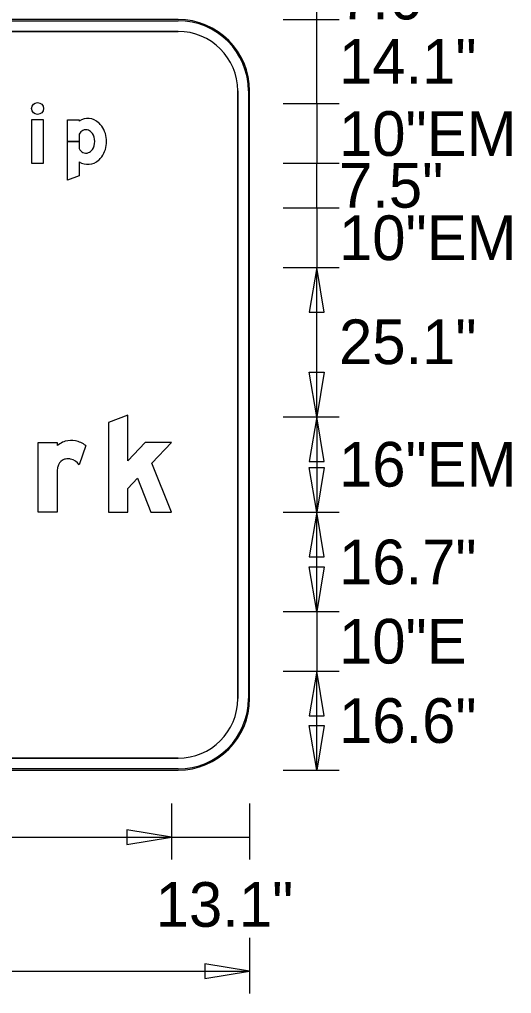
# Model space of a CAD drawing. Extents: x 1806251 to 1809821, y 414895 to 422886.
# Drawn here: x 1809678.349 to 1809679.174, y 414981.376 to 414983.011 of the extents above; entities that cross this region are included whole.
import ezdxf

# ---------------------------------------------------------------- set-up
doc = ezdxf.new("R2010")
doc.units = 0
for name, color, linetype in [('GSBWFILL', 7, 'Continuous'), ('GSCOLORFILL', 7, 'Continuous'), ('GSDIMS', 7, 'Continuous'), ('GSOUTLINE', 7, 'Continuous')]:
    doc.layers.add(name, color=color, linetype=linetype)

msp = doc.modelspace()

# ---------------------------------------------------------------- linework, layer by layer
at = {"layer": 'GSBWFILL'}
for p, q in [((1809678.615, 414983.011), (1809676.574, 414983.011)), ((1809676.574, 414982.991), (1809678.615, 414982.991)), ((1809678.715, 414982.891), (1809678.715, 414981.871)), ((1809678.735, 414981.871), (1809678.735, 414982.891)), ((1809678.4292, 414982.8063), (1809678.4492, 414982.8063)), ((1809678.4492, 414982.8063), (1809678.4292, 414982.8063)), ((1809678.4492, 414982.8183), (1809678.4492, 414982.8063)), ((1809678.4492, 414982.8063), (1809678.4492, 414982.7943)), ((1809678.46, 414982.2958), (1809678.4491, 414982.2632)), ((1809678.615, 414981.771), (1809676.5742, 414981.771)), ((1809676.5742, 414981.751), (1809678.615, 414981.751))]:
    msp.add_line(p, q, dxfattribs=at)
for points in [[(1809678.3692, 414982.7698), (1809678.3892, 414982.7698), (1809678.3892, 414982.8428), (1809678.3692, 414982.8428)], [(1809678.5709, 414982.2663), (1809678.604, 414982.301), (1809678.5598, 414982.301), (1809678.5304, 414982.2701), (1809678.5304, 414982.347), (1809678.4984, 414982.3346), (1809678.4984, 414982.1842), (1809678.5304, 414982.1842), (1809678.5304, 414982.2237), (1809678.5467, 414982.2408), (1809678.5695, 414982.1842), (1809678.604, 414982.1842)]]:
    msp.add_lwpolyline(points, close=True, dxfattribs=at)
for points in [[(1809678.4292, 414982.8063), (1809678.4292, 414982.8428), (1809678.4492, 414982.8428), (1809678.4492, 414982.8404)], [(1809678.4492, 414982.7722), (1809678.4492, 414982.7484), (1809678.4292, 414982.7411), (1809678.4292, 414982.8063)], [(1809678.412, 414982.2488), (1809678.412, 414982.1842), (1809678.38, 414982.1842), (1809678.38, 414982.301), (1809678.412, 414982.301), (1809678.412, 414982.2958)]]:
    msp.add_lwpolyline(points, dxfattribs=at)
for centre, radius, start, end in [((1809678.615, 414982.891), 0.12, 0, 90), ((1809678.615, 414982.891), 0.1, 0, 90), ((1809678.615, 414981.871), 0.12, 270, 0), ((1809678.615, 414981.871), 0.1, 270, 0)]:
    msp.add_arc(centre, radius, start, end, dxfattribs=at)
msp.add_ellipse((1809678.3792, 414982.8616), major_axis=(0, 0.01), ratio=0.999994, dxfattribs=at)
for centre, major_axis, ratio, start_param, end_param in [((1809678.4637, 414982.8186), (0, 0.0262), 0.999998, 5.531582, 6.870178), ((1809678.461, 414982.8136), (0, 0.0317), 0.999998, 5.330424, 5.578482), ((1809678.4603, 414982.8139), (0, 0.012), 0.999998, 5.918977, 7.479923), ((1809678.4596, 414982.812), (0, 0.014), 0.999998, 5.303244, 5.918977), ((1809678.4521, 414982.807), (0, 0.0231), 0.999998, 4.683658, 5.303244), ((1809678.4514, 414982.8063), (0, 0.0437), 0.999998, 4.712389, 5.339507), ((1809678.4521, 414982.8056), (0, 0.0231), 0.999998, 4.121534, 4.74112), ((1809678.4514, 414982.8063), (0, 0.0437), 0.999998, 4.085271, 4.712389), ((1809678.4603, 414982.7987), (0, 0.012), 0.999998, 1.944855, 3.5058), ((1809678.4596, 414982.8006), (0, 0.014), 0.999998, 3.5058, 4.121534), ((1809678.4637, 414982.794), (0, 0.0262), 0.999998, 2.5546, 3.893196), ((1809678.461, 414982.799), (0, 0.0317), 0.999998, 3.846296, 4.094354), ((1809678.4441, 414982.2531), (0, 0.0534), 0.999993, 0.443663, 0.646229), ((1809678.4315, 414982.2797), (0, 0.024), 0.999993, 0.24142, 0.443663), ((1809678.4356, 414982.263), (0, 0.0412), 0.999993, 6.103268, 6.524606), ((1809678.4366, 414982.2681), (0, 0.036), 0.999993, 5.846069, 6.103268), ((1809678.4329, 414982.2602), (0, 0.0447), 0.999993, 5.631644, 5.846069), ((1809678.429, 414982.2575), (0, 0.016), 0.999993, 0.293855, 1.188904), ((1809678.4293, 414982.2564), (0, 0.0171), 0.999993, 0.067293, 0.293855), ((1809678.4299, 414982.2479), (0, 0.0256), 0.999993, 6.094384, 6.350479), ((1809678.4305, 414982.2515), (0, 0.022), 0.999993, 5.27661, 6.094384), ((1809678.4798, 414982.2487), (0, 0.0678), 0.999993, 1.445958, 1.569673), ((1809678.4373, 414982.2541), (0, 0.025), 0.999993, 1.188904, 1.450084)]:
    msp.add_ellipse(centre, major_axis=major_axis, ratio=ratio, start_param=start_param, end_param=end_param, dxfattribs=at)
at = {"layer": 'GSCOLORFILL'}
for p, q in [((1809678.615, 414983.011), (1809676.574, 414983.011)), ((1809678.615, 414983.011), (1809676.574, 414983.011)), ((1809678.615, 414983.011), (1809676.574, 414983.011)), ((1809676.574, 414983.009), (1809678.615, 414983.009)), ((1809676.574, 414982.991), (1809678.615, 414982.991)), ((1809678.715, 414982.891), (1809678.715, 414981.871)), ((1809678.733, 414982.891), (1809678.733, 414981.871)), ((1809678.735, 414981.871), (1809678.735, 414982.891)), ((1809678.735, 414981.871), (1809678.735, 414982.891)), ((1809678.735, 414981.871), (1809678.735, 414982.891)), ((1809678.4292, 414982.8063), (1809678.4492, 414982.8063)), ((1809678.4492, 414982.8063), (1809678.4292, 414982.8063)), ((1809678.4492, 414982.8183), (1809678.4492, 414982.8063)), ((1809678.4492, 414982.8063), (1809678.4492, 414982.7943)), ((1809678.46, 414982.2958), (1809678.4491, 414982.2632)), ((1809678.615, 414981.771), (1809676.5742, 414981.771)), ((1809678.615, 414981.753), (1809676.574, 414981.753)), ((1809676.574, 414981.751), (1809678.615, 414981.751)), ((1809676.574, 414981.751), (1809678.615, 414981.751)), ((1809676.5742, 414981.751), (1809678.615, 414981.751))]:
    msp.add_line(p, q, dxfattribs=at)
for points in [[(1809678.3692, 414982.7698), (1809678.3892, 414982.7698), (1809678.3892, 414982.8428), (1809678.3692, 414982.8428)], [(1809678.5709, 414982.2663), (1809678.604, 414982.301), (1809678.5598, 414982.301), (1809678.5304, 414982.2701), (1809678.5304, 414982.347), (1809678.4984, 414982.3346), (1809678.4984, 414982.1842), (1809678.5304, 414982.1842), (1809678.5304, 414982.2237), (1809678.5467, 414982.2408), (1809678.5695, 414982.1842), (1809678.604, 414982.1842)]]:
    msp.add_lwpolyline(points, close=True, dxfattribs=at)
for points in [[(1809678.4292, 414982.8063), (1809678.4292, 414982.8428), (1809678.4492, 414982.8428), (1809678.4492, 414982.8404)], [(1809678.4492, 414982.7722), (1809678.4492, 414982.7484), (1809678.4292, 414982.7411), (1809678.4292, 414982.8063)], [(1809678.412, 414982.2488), (1809678.412, 414982.1842), (1809678.38, 414982.1842), (1809678.38, 414982.301), (1809678.412, 414982.301), (1809678.412, 414982.2958)]]:
    msp.add_lwpolyline(points, dxfattribs=at)
for centre, radius, start, end in [((1809678.615, 414982.891), 0.12, 0, 90), ((1809678.615, 414982.891), 0.12, 0, 90), ((1809678.615, 414982.891), 0.12, 0, 90), ((1809678.615, 414982.891), 0.118, 0, 90), ((1809678.615, 414982.891), 0.1, 0, 90), ((1809678.615, 414981.871), 0.12, 270, 0), ((1809678.615, 414981.871), 0.12, 270, 0), ((1809678.615, 414981.871), 0.1, 270, 0), ((1809678.615, 414981.871), 0.12, 270, 0), ((1809678.615, 414981.871), 0.118, 270, 0)]:
    msp.add_arc(centre, radius, start, end, dxfattribs=at)
msp.add_ellipse((1809678.3792, 414982.8616), major_axis=(0, 0.01), ratio=0.999994, dxfattribs=at)
for centre, major_axis, ratio, start_param, end_param in [((1809678.4637, 414982.8186), (0, 0.0262), 0.999998, 5.531582, 6.870178), ((1809678.461, 414982.8136), (0, 0.0317), 0.999998, 5.330424, 5.578482), ((1809678.4603, 414982.8139), (0, 0.012), 0.999998, 5.918977, 7.479923), ((1809678.4596, 414982.812), (0, 0.014), 0.999998, 5.303244, 5.918977), ((1809678.4521, 414982.807), (0, 0.0231), 0.999998, 4.683658, 5.303244), ((1809678.4514, 414982.8063), (0, 0.0437), 0.999998, 4.712389, 5.339507), ((1809678.4521, 414982.8056), (0, 0.0231), 0.999998, 4.121534, 4.74112), ((1809678.4514, 414982.8063), (0, 0.0437), 0.999998, 4.085271, 4.712389), ((1809678.4603, 414982.7987), (0, 0.012), 0.999998, 1.944855, 3.5058), ((1809678.4596, 414982.8006), (0, 0.014), 0.999998, 3.5058, 4.121534), ((1809678.4637, 414982.794), (0, 0.0262), 0.999998, 2.5546, 3.893196), ((1809678.461, 414982.799), (0, 0.0317), 0.999998, 3.846296, 4.094354), ((1809678.4441, 414982.2531), (0, 0.0534), 0.999993, 0.443663, 0.646229), ((1809678.4315, 414982.2797), (0, 0.024), 0.999993, 0.24142, 0.443663), ((1809678.4356, 414982.263), (0, 0.0412), 0.999993, 6.103268, 6.524606), ((1809678.4366, 414982.2681), (0, 0.036), 0.999993, 5.846069, 6.103268), ((1809678.4329, 414982.2602), (0, 0.0447), 0.999993, 5.631644, 5.846069), ((1809678.429, 414982.2575), (0, 0.016), 0.999993, 0.293855, 1.188904), ((1809678.4293, 414982.2564), (0, 0.0171), 0.999993, 0.067293, 0.293855), ((1809678.4299, 414982.2479), (0, 0.0256), 0.999993, 6.094384, 6.350479), ((1809678.4305, 414982.2515), (0, 0.022), 0.999993, 5.27661, 6.094384), ((1809678.4798, 414982.2487), (0, 0.0678), 0.999993, 1.445958, 1.569673), ((1809678.4373, 414982.2541), (0, 0.025), 0.999993, 1.188904, 1.450084)]:
    msp.add_ellipse(centre, major_axis=major_axis, ratio=ratio, start_param=start_param, end_param=end_param, dxfattribs=at)
at = {"layer": 'GSDIMS'}
for p, q in [((1809678.8475, 414983.011), (1809678.8475, 414983.0866)), ((1809678.7913, 414983.011), (1809678.885, 414983.011)), ((1809678.7913, 414983.011), (1809678.885, 414983.011)), ((1809678.8475, 414982.8698), (1809678.8475, 414983.011)), ((1809678.7913, 414982.8698), (1809678.885, 414982.8698)), ((1809678.7913, 414982.8698), (1809678.885, 414982.8698)), ((1809678.8475, 414982.8698), (1809678.8475, 414982.7698)), ((1809678.7913, 414982.7698), (1809678.885, 414982.7698)), ((1809678.7913, 414982.7698), (1809678.885, 414982.7698)), ((1809678.8475, 414982.6948), (1809678.8475, 414982.7698)), ((1809678.7913, 414982.6948), (1809678.885, 414982.6948)), ((1809678.7913, 414982.6948), (1809678.885, 414982.6948)), ((1809678.8475, 414982.6948), (1809678.8475, 414982.5948)), ((1809678.7913, 414982.5948), (1809678.885, 414982.5948)), ((1809678.7913, 414982.5948), (1809678.885, 414982.5948)), ((1809678.8475, 414982.3442), (1809678.8475, 414982.5948)), ((1809678.7913, 414982.3442), (1809678.885, 414982.3442)), ((1809678.7913, 414982.3442), (1809678.885, 414982.3442)), ((1809678.8475, 414982.3442), (1809678.8475, 414982.1842)), ((1809678.7913, 414982.1842), (1809678.885, 414982.1842)), ((1809678.7913, 414982.1842), (1809678.885, 414982.1842)), ((1809678.8475, 414982.0172), (1809678.8475, 414982.1842)), ((1809678.7913, 414982.0172), (1809678.885, 414982.0172)), ((1809678.7913, 414982.0172), (1809678.885, 414982.0172)), ((1809678.8475, 414982.0172), (1809678.8475, 414981.9172)), ((1809678.7913, 414981.9172), (1809678.885, 414981.9172)), ((1809678.7913, 414981.9172), (1809678.885, 414981.9172)), ((1809678.8475, 414981.751), (1809678.8475, 414981.9172)), ((1809678.7913, 414981.751), (1809678.885, 414981.751)), ((1809678.604, 414981.6948), (1809678.604, 414981.601)), ((1809678.604, 414981.6948), (1809678.604, 414981.601)), ((1809678.735, 414981.6948), (1809678.735, 414981.601)), ((1809676.5848, 414981.6385), (1809678.604, 414981.6385)), ((1809678.604, 414981.6385), (1809678.735, 414981.6385)), ((1809678.735, 414981.4697), (1809678.735, 414981.376)), ((1809676.454, 414981.4135), (1809678.735, 414981.4135))]:
    msp.add_line(p, q, dxfattribs=at)
for points in [[(1809678.8475, 414982.5948), (1809678.835, 414982.5198), (1809678.86, 414982.5198)], [(1809678.8475, 414982.3442), (1809678.835, 414982.4192), (1809678.86, 414982.4192)], [(1809678.8475, 414982.3442), (1809678.835, 414982.2692), (1809678.86, 414982.2692)], [(1809678.8475, 414982.1842), (1809678.835, 414982.2592), (1809678.86, 414982.2592)], [(1809678.8475, 414982.1842), (1809678.835, 414982.1092), (1809678.86, 414982.1092)], [(1809678.8475, 414982.0172), (1809678.835, 414982.0922), (1809678.86, 414982.0922)], [(1809678.8475, 414981.9172), (1809678.835, 414981.8422), (1809678.86, 414981.8422)], [(1809678.8475, 414981.751), (1809678.835, 414981.826), (1809678.86, 414981.826)], [(1809678.604, 414981.6385), (1809678.529, 414981.651), (1809678.529, 414981.626)], [(1809678.735, 414981.4135), (1809678.66, 414981.426), (1809678.66, 414981.401)]]:
    msp.add_lwpolyline(points, close=True, dxfattribs=at)
at = {"layer": 'GSOUTLINE'}
for p, q in [((1809678.615, 414983.011), (1809676.574, 414983.011)), ((1809678.615, 414982.991), (1809676.574, 414982.991)), ((1809678.715, 414981.871), (1809678.715, 414982.891)), ((1809678.735, 414981.871), (1809678.735, 414982.891)), ((1809678.4492, 414982.8183), (1809678.4492, 414982.7943)), ((1809678.46, 414982.2958), (1809678.4491, 414982.2632)), ((1809676.574, 414981.771), (1809678.615, 414981.771)), ((1809676.574, 414981.751), (1809678.615, 414981.751))]:
    msp.add_line(p, q, dxfattribs=at)
for points in [[(1809678.3692, 414982.7698), (1809678.3892, 414982.7698), (1809678.3892, 414982.8428), (1809678.3692, 414982.8428)], [(1809678.5709, 414982.2663), (1809678.604, 414982.301), (1809678.5598, 414982.301), (1809678.5304, 414982.2701), (1809678.5304, 414982.347), (1809678.4984, 414982.3346), (1809678.4984, 414982.1842), (1809678.5304, 414982.1842), (1809678.5304, 414982.2237), (1809678.5467, 414982.2408), (1809678.5695, 414982.1842), (1809678.604, 414982.1842)]]:
    msp.add_lwpolyline(points, close=True, dxfattribs=at)
for points in [[(1809678.4492, 414982.7722), (1809678.4492, 414982.7484), (1809678.4292, 414982.7411), (1809678.4292, 414982.8428), (1809678.4492, 414982.8428), (1809678.4492, 414982.8404)], [(1809678.412, 414982.2488), (1809678.412, 414982.1842), (1809678.38, 414982.1842), (1809678.38, 414982.301), (1809678.412, 414982.301), (1809678.412, 414982.2958)]]:
    msp.add_lwpolyline(points, dxfattribs=at)
for centre, radius, start, end in [((1809678.615, 414982.891), 0.12, 0, 90), ((1809678.615, 414982.891), 0.1, 0, 90), ((1809678.615, 414981.871), 0.12, 270, 0), ((1809678.615, 414981.871), 0.1, 270, 0)]:
    msp.add_arc(centre, radius, start, end, dxfattribs=at)
msp.add_ellipse((1809678.3792, 414982.8616), major_axis=(0, 0.01), ratio=0.999994, dxfattribs=at)
for centre, major_axis, ratio, start_param, end_param in [((1809678.4637, 414982.8186), (0, 0.0262), 0.999998, 5.531582, 6.870178), ((1809678.461, 414982.8136), (0, 0.0317), 0.999998, 5.330424, 5.578482), ((1809678.4603, 414982.8139), (0, 0.012), 0.999998, 5.918977, 7.479923), ((1809678.4596, 414982.812), (0, 0.014), 0.999998, 5.303244, 5.918977), ((1809678.4521, 414982.807), (0, 0.0231), 0.999998, 4.683658, 5.303244), ((1809678.4514, 414982.8063), (0, 0.0437), 0.999998, 4.712389, 5.339507), ((1809678.4521, 414982.8056), (0, 0.0231), 0.999998, 4.121534, 4.74112), ((1809678.4514, 414982.8063), (0, 0.0437), 0.999998, 4.085271, 4.712389), ((1809678.4603, 414982.7987), (0, 0.012), 0.999998, 1.944855, 3.5058), ((1809678.4596, 414982.8006), (0, 0.014), 0.999998, 3.5058, 4.121534), ((1809678.4637, 414982.794), (0, 0.0262), 0.999998, 2.5546, 3.893196), ((1809678.461, 414982.799), (0, 0.0317), 0.999998, 3.846296, 4.094354), ((1809678.4441, 414982.2531), (0, 0.0534), 0.999993, 0.443663, 0.646229), ((1809678.4315, 414982.2797), (0, 0.024), 0.999993, 0.24142, 0.443663), ((1809678.4356, 414982.263), (0, 0.0412), 0.999993, 6.103268, 6.524606), ((1809678.4366, 414982.2681), (0, 0.036), 0.999993, 5.846069, 6.103268), ((1809678.4329, 414982.2602), (0, 0.0447), 0.999993, 5.631644, 5.846069), ((1809678.429, 414982.2575), (0, 0.016), 0.999993, 0.293855, 1.188904), ((1809678.4293, 414982.2564), (0, 0.0171), 0.999993, 0.067293, 0.293855), ((1809678.4299, 414982.2479), (0, 0.0256), 0.999993, 6.094384, 6.350479), ((1809678.4305, 414982.2515), (0, 0.022), 0.999993, 5.27661, 6.094384), ((1809678.4798, 414982.2487), (0, 0.0678), 0.999993, 1.445958, 1.569673), ((1809678.4373, 414982.2541), (0, 0.025), 0.999993, 1.188904, 1.450084)]:
    msp.add_ellipse(centre, major_axis=major_axis, ratio=ratio, start_param=start_param, end_param=end_param, dxfattribs=at)

# ---------------------------------------------------------------- texts
at = {"layer": 'GSDIMS'}
for s, p in [('7.6"', (1809678.885, 414983.0111)), ('14.1"', (1809678.885, 414982.9033)), ('10"EM', (1809678.885, 414982.7821)), ('7.5"', (1809678.885, 414982.6951)), ('10"EM', (1809678.885, 414982.6071)), ('25.1"', (1809678.885, 414982.4325)), ('16"EM', (1809678.885, 414982.2269)), ('16.7"', (1809678.885, 414982.0629)), ('10"E', (1809678.885, 414981.9299)), ('16.6"', (1809678.885, 414981.7967)), ('13.1"', (1809678.5775, 414981.488))]:
    msp.add_text(s, height=0.075, dxfattribs=at).set_placement(p)

doc.saveas('drawing.dxf')
